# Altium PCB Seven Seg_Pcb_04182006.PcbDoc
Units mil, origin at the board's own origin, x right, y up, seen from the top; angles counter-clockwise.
Board outline 3624 x 2321 mil, 2 copper layers (Top Layer, Bottom Layer); 33 components, 44 nets, 144 pads, 3 vias.
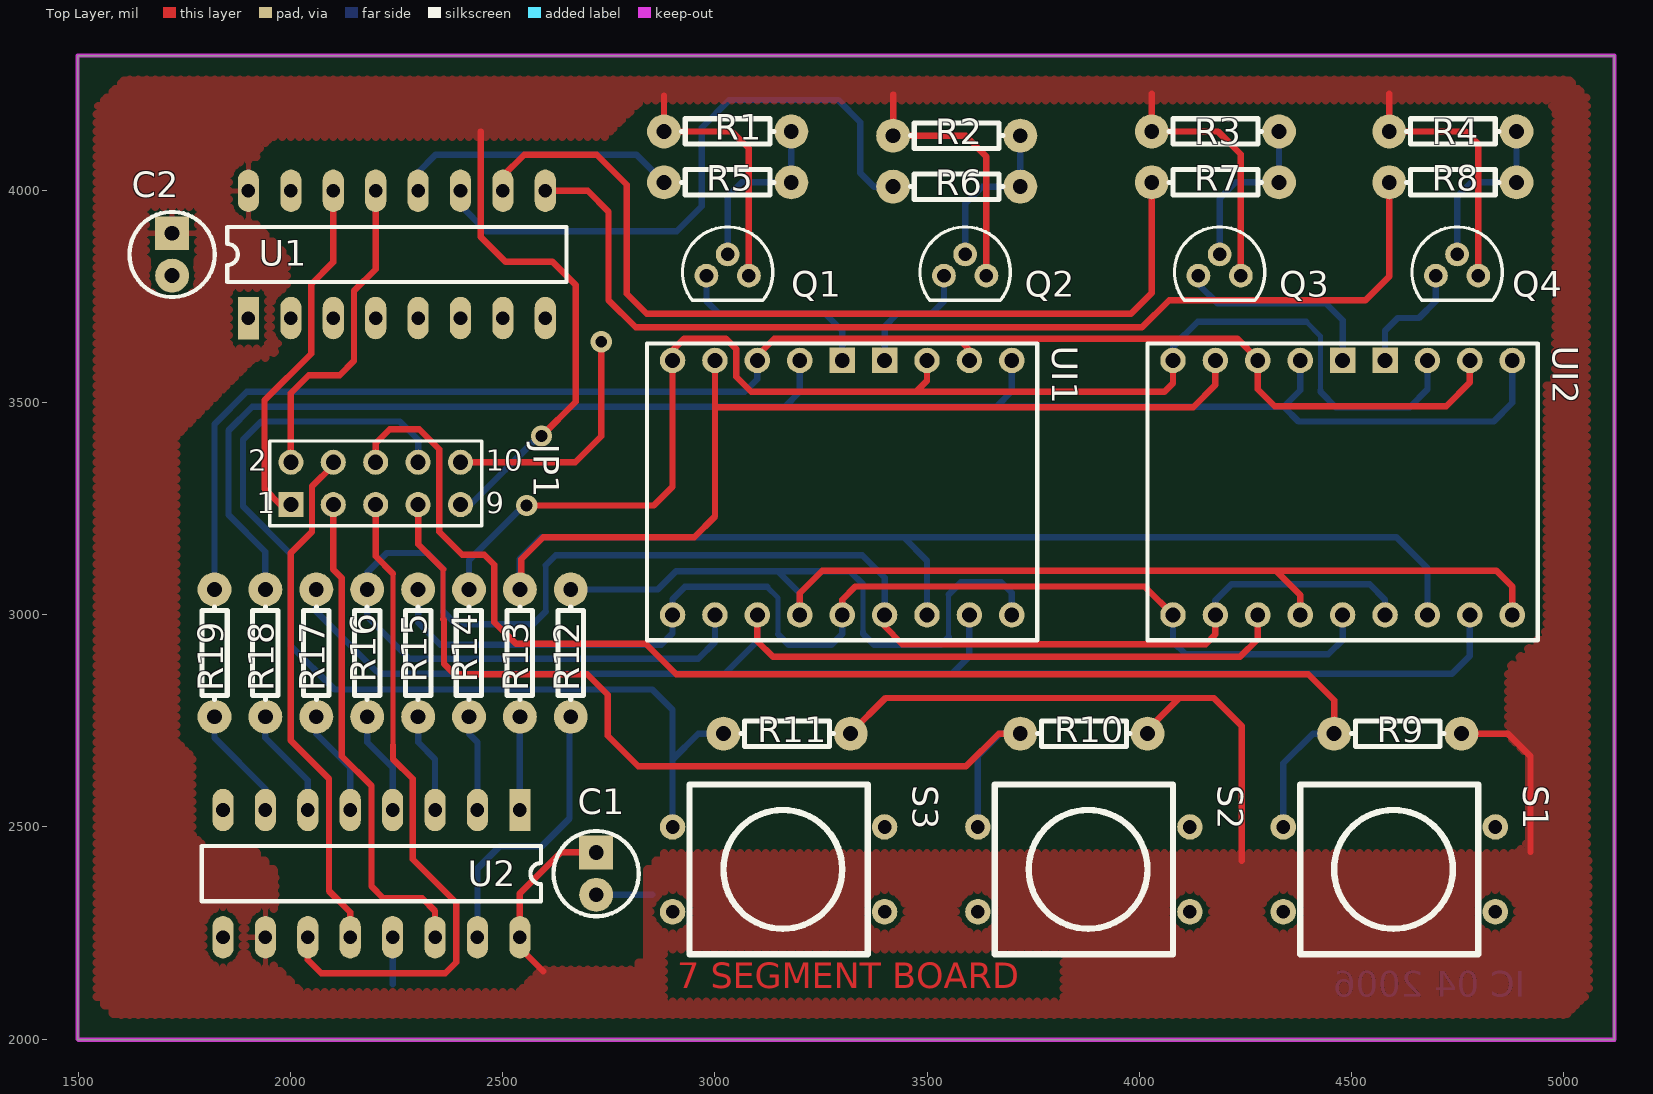
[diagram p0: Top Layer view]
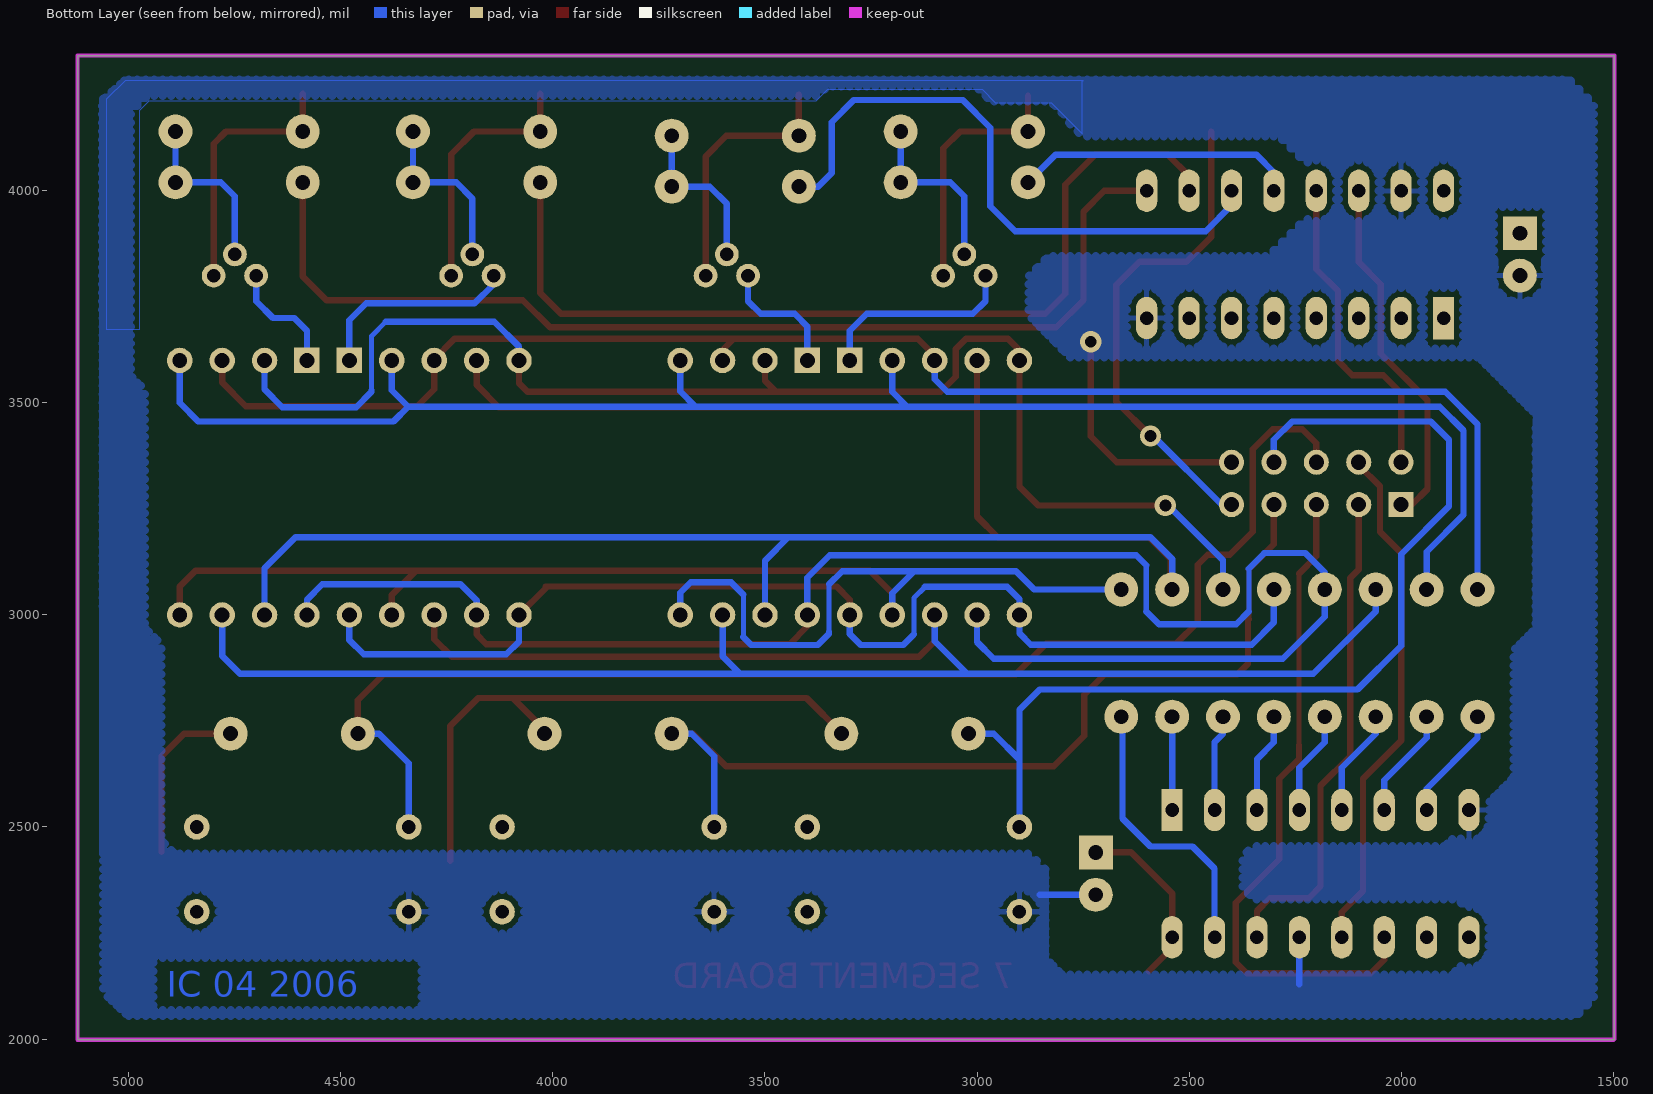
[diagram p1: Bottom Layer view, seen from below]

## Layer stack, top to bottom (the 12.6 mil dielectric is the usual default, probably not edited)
Top Layer: signal copper 1.4
Dielectric: dielectric 12.6, FR-4, Dk 4.8
Bottom Layer: signal copper 1.4

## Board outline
1497,4319 5121,4319 5121,1998 1497,1998

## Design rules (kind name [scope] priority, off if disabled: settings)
Clearance [All] p1: gap=12
ComponentClearance [All] p1: gap=10 collisioncheckmode=0
PlaneConnect [All] p1: planeconnectstyle=Relief reliefexpansion=20 reliefentries=4 reliefconductorwidth=12 reliefairgap=12
PolygonConnect [All] p1: connectstyle=Relief reliefconductorwidth=12 reliefentries=4 polygonreliefangle="90 Angle"
RoomDefinition SevenSeg_Sch_04172006 [InComponentClass('SevenSeg_Sch_04172006')] p1: confinementstyle=ConfineIn formatcopy=TRUE outline 1499,1997 5123,1997 5123,4324 1499,4324
RoutingLayers [All] p1: top layer=Horizontal bottom layer=Vertical
RoutingVias [All] p1: holewidth=28 width=50 viastyle="Through Hole" minholewidth=28 minwidth=50 maxholewidth=28 maxwidth=50
SolderMaskExpansion [All] p1: expansion=4
TestPointUsage [All] p1: valid=0 allowmultiple=FALSE
Testpoint [All] p1: side=15 testpointundercomponent=TRUE minsize=40 maxsize=100 preferedsize=60 minholesize=0 maxholesize=40 preferedholesize=32 testpointgrid=1 style=1023 order=-539222988
Width [All] p1: maxlimit=20 minlimit=12 preferedwidth=15
15 further rules are at their usual default settings.

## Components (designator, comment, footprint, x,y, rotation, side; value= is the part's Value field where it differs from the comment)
C1 "100nF" "CAP Circ/0.1" 2720,2440 r90 top
C2 "100nF" "CAP Circ/0.1" 1720,3900 r90 top
JP1 "Header 5X2" HDR2X5 2000,3260 r0 top
Q1 "PNP" BC548 3080,3800 r90 top
Q2 "PNP" BC548 3640,3800 r90 top
Q3 "PNP" BC548 4240,3800 r90 top
Q4 "PNP" BC548 4800,3800 r90 top
R1 "10K" RES 3180,4140 r180 top
R2 "10K" RES 3720,4130 r180 top
R3 "10K" RES 4330,4140 r180 top
R4 "10K" RES 4890,4140 r180 top
R5 "10K" RES 2880,4020 r0 top
R6 "10K" RES 3420,4010 r0 top
R7 "10K" RES 4030,4020 r0 top
R8 "10K" RES 4590,4020 r0 top
R9 "10k" RES 4460,2720 r0 top
R10 "10K" RES 3720,2720 r0 top
R11 "10K" RES 3020,2720 r0 top
R12 "220" RES 2660,2760 r90 top
R13 "220" RES 2540,2760 r90 top
R14 "220" RES 2420,2760 r90 top
R15 "220" RES 2300,2760 r90 top
R16 "220" RES 2180,2760 r90 top
R17 "220" RES 2060,2760 r90 top
R18 "220" RES 1940,2760 r90 top
R19 "220" RES 1820,2760 r90 top
S1 "SWITCH PB2" "SWITCH PB2" 4340,2500 r0 top
S2 "SWITCH PB2" "SWITCH PB2" 3620,2500 r0 top
S3 "SWITCH PB2" "SWITCH PB2" 2900,2500 r0 top
U1 "74HC139" DIP16 1900,3700 r90 top
U2 "74HC595" DIP16 2540,2540 r270 top
UI1 "SEVENSEG 2CA" SEVENTSEGMENT2 2900,3600 r0 top
UI2 "SEVENSEG 2CA" SEVENTSEGMENT2 4080,3600 r0 top

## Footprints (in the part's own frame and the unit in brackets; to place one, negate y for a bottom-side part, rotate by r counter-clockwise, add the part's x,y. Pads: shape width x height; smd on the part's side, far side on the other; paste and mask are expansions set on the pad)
BC548 [mil]
  round 56 hole 32: 1(0,0) 2(50,50) 3(0,100)
  silkscreen extent -59,-57 115,157
"CAP Circ/0.1" [mil]
  rect 80x80 hole 35: 1(0,0)
  round 80 hole 35: 2(-100,0)
  silkscreen extent -150,-100 50,100
DIP16 [mil]
  rect 100x50 hole 32: 1(0,0)
  oval 100x50 hole 32: 2(0,-100) 3(0,-200) 4(0,-300) 5(0,-400) 6(0,-500) 7(0,-600) 8(0,-700) 9(300,-700) 10(300,-600) 11(300,-500) 12(300,-400) 13(300,-300) 14(300,-200) 15(300,-100) 16(300,0)
  silkscreen extent 85,-750 215,50
HDR2X5 [mm]
  rect 1.5x1.5 hole 0.9: 1(0,0)
  round 1.5 hole 0.9: 2(0,2.54) 3(2.54,0) 4(2.54,2.54) 5(5.08,0) 6(5.08,2.54) 7(7.62,0) 8(7.62,2.54) 9(10.16,0) 10(10.16,2.54)
  silkscreen extent -1.27,-1.27 11.43,3.81
RES [mil]
  round 80 hole 35: 1(0,0) 2(300,0)
  silkscreen extent 41,-30 259,30
SEVENTSEGMENT2 [mil]
  round 60 hole 35: 1(0,0) 2(100,0) 3(200,0) 4(300,0) 7(600,0) 8(700,0) 9(800,0) 10(800,-600) 11(700,-600) 12(600,-600) 13(500,-600) 14(400,-600) 15(300,-600) 16(200,-600) 17(100,-600) 18(0,-600)
  rect 60x60 hole 35: 5(400,0) 6(500,0)
  silkscreen extent -60,-660 860,40
"SWITCH PB2" [mil]
  round 60 hole 32: 1(0,0) 2(0,-200) 3(500,0) 4(500,-200)
  silkscreen extent 40,-300 460,100

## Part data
C1 C2: library part CAPACITOR, "Capacitor"
JP1: "Header, 5-Pin, Dual row"
Q1 Q2 Q3 Q4: "PNP Transistor"
R1 R2 R3 R4 R5 R6 R7 R8 R9 R10 R11 R12 R13 R14 R15 R16 R17 R18 R19: library part RES
U1: "2-to-4 Decoder"
U2: "8 Bit Shift Register with Output Latches (3 STATE)"

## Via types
v1: diameter 50, hole 28, Top Layer to Bottom Layer, 3 vias

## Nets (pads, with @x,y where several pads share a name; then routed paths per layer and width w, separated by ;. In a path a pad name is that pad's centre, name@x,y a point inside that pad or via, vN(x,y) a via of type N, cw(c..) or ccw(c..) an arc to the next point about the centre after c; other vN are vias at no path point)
COM1: Q4.3 UI2.6 | length 279
  Bottom Layer w15: UI2.6 4580,3670 4610,3700 4660,3700 4700,3740 Q4.3
COM2: Q3.3 UI2.5 | length 490.2
  Bottom Layer w15: Q3.3 4140,3780 4185,3735 4440,3735 4480,3695 UI2.5
COM3: Q2.3 UI1.6 | length 304.9
  Bottom Layer w15: UI1.6 3400,3680 3430,3710 3510,3710 3540,3740 Q2.3
COM4: Q1.3 UI1.5 | length 479
  Bottom Layer w15: Q1.3 2980,3740 3010,3710 3260,3710 3300,3670 UI1.5
DEC0: JP1.2 U1.13 | length 765.6
  Top Layer w15: JP1.2 2000,3523 2042,3565 2115,3565 2149,3599 2149,3764 2200,3815 U1.13
DEC1: JP1.1 U1.14 | length 847.4
  Top Layer w15: JP1.1 1975,3260 1938,3297 1938,3506 2048,3616 2048,3780 2100,3832 U1.14
DSER: JP1.3 U2.14 | length 1173.3
  Top Layer w15: JP1.3 2100,3107 2120,3087 2120,2667 2190,2597 2190,2360 2218,2332 2310,2332 2340,2302 U2.14
GND: C1.2 C2.2 JP1.10 S1.2 S2.2 S3.2 U1.8 U1.15 U2.8 U2.13 | length 823.3
  Top Layer w15: JP1.10 2671,3360 2732,3421 v1(2732,3644)
  Bottom Layer w15: 2240,2129 U2.13 ; C1.2 2852,2340
LED1: R19.2 UI1.3 UI1.8 UI2.3 UI2.8 | length 3709.9
  Top Layer w15: UI1.3 3100,3611 3140,3651 4232,3651 4280,3603 4280,3532 4320,3492 4724,3492 4780,3548 UI2.8 ; 3574,3651 3600,3625 UI1.8
  Bottom Layer w15: R19.2 1820,3450 1896,3526 3070,3526 3100,3556 UI1.3
LED2: R18.2 UI1.4 UI1.9 UI2.4 UI2.9 | length 3966.5
  Bottom Layer w15: R18.2 1940,3149 1853,3236 1853,3435 1909,3491 4341,3491 ; 3165,3491 3200,3526 UI1.4 ; 3664,3491 3700,3527 UI1.9 ; UI2.4 4380,3530 4341,3491 ; UI2.9 4880,3500 4836,3456 4376,3456 4341,3491
LED3: R17.2 UI1.11 UI1.16 UI2.11 UI2.16 | length 4605.9
  Top Layer w15: UI1.16 3100,2938 3137,2901 4238,2901 4280,2943 UI2.16
  Bottom Layer w15: R17.2 2060,3008 2207,2861 4738,2861 4780,2903 UI2.11 ; 3023,2861 3100,2938 UI1.16 ; 3559,2861 3600,2902 UI1.11
LED4: R16.2 UI1.13 UI1.17 UI2.13 UI2.17 | length 4035.4
  Top Layer w15: UI1.13 3400,2973 3442,2931 4157,2931 4180,2954 UI2.17
  Bottom Layer w12: 2359,3008 2359,3109 ; 2601,3008 2601,3117
  Bottom Layer w15: 2359,3008 2389,2978 2571,2978 2601,3008 ; 2359,3109 2323,3145 2323,3146 2226,3146 2180,3100 2180,2996 2279,2897 2961,2897 3000,2936 UI1.17 ; 2601,3117 2625,3141 3347,3141 3400,3088 UI1.13 ; UI2.17 4180,3034 4218,3072 4544,3072 4580,3036 UI2.13
LED5: R15.2 UI1.14 UI1.18 UI2.14 UI2.18 | length 2773.1
  Top Layer w15: UI1.14 3300,3036 3331,3067 4017,3067 4017,3063 UI2.18
  Bottom Layer w12: 3123,3066 3149,3040 3149,2954
  Bottom Layer w15: R15.2 2300,2982 2352,2930 2873,2930 2900,2957 2900,3037 2929,3066 3123,3066 ; 3149,2954 3174,2929 3274,2929 3300,2955 UI1.14 ; UI2.18 4080,2937 4110,2907 4446,2907 4480,2941 UI2.14
LED6: R14.2 UI1.1 UI1.7 UI2.1 UI2.7 | length 3273.2
  Top Layer w15: v1(2556,3258) 2856,3258 2900,3302 2900,3624 2927,3651 3026,3651 3050,3627 3050,3562 3086,3526 4060,3526 4080,3546 UI2.1 ; 3474,3526 3500,3552 UI1.7
  Bottom Layer w12: 4394,3691 4428,3657 4428,3530
  Bottom Layer w15: R14.2 2420,3129 2549,3258 v1(2556,3258) ; UI2.1 4080,3633 4138,3691 4394,3691 ; 4428,3530 4428,3526 4464,3490 4638,3490 4680,3532 UI2.7
LED7: R13.2 UI1.2 UI1.12 UI2.2 UI2.12 | length 4777.8
  Top Layer w15: R13.2 2543,3063 2543,3131 2595,3183 2951,3183 3000,3232 UI1.2 ; 3000,3490 4128,3490 4180,3542 UI2.2
  Bottom Layer w15: R13.2 2540,3132 2591,3183 4607,3183 4680,3110 UI2.12 ; 3445,3183 3500,3128 UI1.12
LED8: R12.2 UI1.10 UI1.15 UI2.10 UI2.15 | length 3467.5
  Top Layer w15: UI1.15 3200,3051 3253,3104 4843,3104 4880,3067 UI2.10 ; 4323,3104 4380,3047 UI2.15
  Bottom Layer w12: 3349,2960 3349,3072 ; 3551,2948 3551,3048
  Bottom Layer w15: R12.2 2865,3060 2908,3103 3318,3103 3349,3072 ; 3148,3103 3200,3051 UI1.15 ; 3349,2960 3349,2956 3376,2929 3532,2929 3551,2948 ; 3551,3048 3580,3077 3675,3077 3700,3052 UI1.10
LSD1: R8.1 U1.9 | length 2517.5
  Top Layer w15: U1.9 2700,4000 2749,3951 2749,3742 2813,3678 4007,3678 4071,3742 4534,3742 4590,3798 R8.1
LSD2: R6.1 U1.11 | length 1470.4
  Bottom Layer w15: U1.11 2400,3966 2461,3905 2910,3905 2969,3964 2969,4149 3034,4214 3291,4214 3343,4162 3343,4042 3375,4010 R6.1
MSD1: R7.1 U1.10 | length 2172.9
  Top Layer w15: U1.10 2500,4035 2550,4085 2721,4085 2792,4014 2792,3757 2839,3710 3981,3710 4030,3759 R7.1
MSD2: R5.1 U1.12 | length 667.9
  Bottom Layer w15: U1.12 2300,4044 2341,4085 2815,4085 R5.1
NetQ1_2: Q1.2 R1.1 R5.2 | length 420.7
  Bottom Layer w15: Q1.2 3030,3987 3063,4020 R5.2 R1.1
NetQ2_2: Q2.2 R2.1 R6.2 | length 386.6
  Bottom Layer w15: Q2.2 3590,3970 3630,4010 R6.2 R2.1
NetQ3_2: Q3.2 R3.1 R7.2 | length 407.7
  Bottom Layer w15: Q3.2 4190,3982 4228,4020 R7.2 R3.1
NetQ4_2: Q4.2 R4.1 R8.2 | length 410.7
  Bottom Layer w15: Q4.2 4750,3987 4783,4020 R8.2 R4.1
NetR12_1: R12.1 U2.15 | length 677.9
  Bottom Layer w15: U2.15 2440,2402 2492,2454 2591,2454 2657,2520 R12.1@2657,2770
NetR13_1: R13.1 U2.1 | length 220
  Bottom Layer w15: U2.1 R13.1
NetR14_1: R14.1 U2.2 | length 228.3
  Bottom Layer w15: R14.1 2420,2720 2440,2700 U2.2
NetR15_1: R15.1 U2.3 | length 236.6
  Bottom Layer w15: R15.1 2300,2700 2340,2660 U2.3
NetR16_1: R16.1 U2.4 | length 244.9
  Bottom Layer w15: R16.1 2180,2700 2240,2640 U2.4
NetR17_1: R17.1 U2.5 | length 253.1
  Bottom Layer w15: R17.1 2060,2720 2140,2640 U2.5
NetR18_1: R18.1 U2.6 | length 261.4
  Bottom Layer w15: R18.1 1940,2710 2040,2610 U2.6
NetR19_1: R19.1 U2.7 | length 269.7
  Bottom Layer w15: R19.1 1820,2710 1940,2590 U2.7
NetU1_2: U1.2
NetU1_3: U1.3
NetU1_4: U1.4
NetU1_5: U1.5
NetU1_6: U1.6
NetU1_7: U1.7
SHCLK: JP1.5 U2.11 | length 1584.7
  Top Layer w12: 2241,2693 2241,3097
  Top Layer w15: U2.11 2040,2187 2072,2155 2364,2155 2390,2181 2390,2321 2287,2424 2287,2614 2241,2660 2241,2693 ; JP1.5 2200,3138 2241,3097
STCLK: JP1.4 U2.12 | length 1219.4
  Top Layer w15: JP1.4 2100,3353 2050,3303 2050,3196 2000,3146 2000,2704 2090,2614 2090,2349 2140,2299 U2.12
SW1: JP1.6 R9.1 S1.1 | length 3155.7
  Top Layer w15: JP1.6@2201,3360 JP1.6 2200,3405 2233,3438 2303,3438 2350,3391 2350,3196 2404,3142 2456,3142 2480,3118 2480,2983 2531,2932 2837,2932 2909,2860 4399,2860 4460,2799 R9.1
  Bottom Layer w15: S1.1 4340,2650 4410,2720 R9.1
SW2: JP1.7 R10.1 S2.1 | length 2237.2
  Top Layer w12: 2359,2990 2359,3108
  Top Layer w15: JP1.7 2300,3167 2359,3108 ; 2359,2990 2361,2988 2361,2885 2386,2860 2699,2860 2747,2812 2747,2715 2819,2643 3592,2643 3669,2720 R10.1
  Bottom Layer w15: S2.1 3620,2667 3673,2720 R10.1
SW3: JP1.8 R11.1 S3.1 | length 2418.2
  Bottom Layer w15: JP1.8 2300,3413 2257,3456 1930,3456 1887,3413 1887,3256 2000,3143 2000,2927 2103,2824 2852,2824 2900,2776 S3.1 ; 2900,2659 2961,2720 R11.1
VCC: C1.1 C2.1 JP1.9 Q1.1 Q2.1 Q3.1 Q4.1 R1.2 R2.2 R3.2 R4.2 R9.2 R10.2 R11.2 U1.16 U2.10 U2.16 | length 5871
  Top Layer w15: 2448,4140 2448,3891 2506,3833 2617,3833 2672,3778 2672,3503 v1(2591,3422) ; 2595,2160 2540,2215 2540,2343 2637,2440 C1.1 ; 2880,4224 R1.2 3040,4140 3080,4100 Q1.1 ; R11.2 3320,2722 3402,2804 4176,2804 4242,2738 4242,2420 ; 3420,4227 R2.2 3591,4130 3640,4081 Q2.1 ; R10.2 4020,2729 4095,2804 ; 4030,4229 R3.2 4186,4140 4240,4086 Q3.1 ; 4590,4229 R4.2 4771,4140 4800,4111 Q4.1 ; R9.2 4870,2720 4923,2667 4923,2441
  Bottom Layer w15: JP1.9 2423,3260 2585,3422 v1(2591,3422)
pads on no net: S1.3 S1.4 S2.3 S2.4 S3.3 S3.4 U1.1 U2.9

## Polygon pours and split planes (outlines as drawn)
VCC on Top Layer (hatched 90Degree grid 20 track 20, remove dead copper): 1541,4195 1608,4262 5013,4262 5056,4219 5056,3677 4982,3677 4982,4192 4960,4214 2827,4214 2740,4127 1954,4127 1919,4092 1919,3911 1926,3911 1990,3847 1990,3648 1948,3606 1822,3606 1668,3452 1542,3452 1542,4190
VCC on Top Layer (hatched 90Degree grid 20 track 20, remove dead copper): 1948,3606 1542,3606 1542,2099 1584,2057 5006,2057 5060,2109 5059,2438 2879,2438 2840,2399 2840,2200 2803,2163 2590,2163 2537,2110 2025,2110 1963,2172 1963,2395 1914,2444 1805,2444 1767,2482 1767,2664 1730,2701 1730,3422 1914,3606
VCC on Top Layer (hatched 90Degree grid 20 track 20): 4891,2438 4920,2467 4920,2667 4870,2717 4870,2872 4931,2933 4961,2963 4961,3542 4981,3562 4981,3677 5056,3677 5056,2438
GND on Bottom Layer (hatched 90Degree grid 20 track 20, remove dead copper): 1548,4207 1603,4262 2756,4262 2785,4233 2785,4162 2752,4129 2289,4129 2226,4066 2226,3934 2314,3846 2831,3846 2878,3799 2878,3707 2781,3607 1816.98,3606.98 1666,3456 1546,3456 1546,4205
GND on Bottom Layer (hatched 90Degree grid 20 track 20, remove dead copper): 1546,3466 1546,2095 1586,2055 5002,2055 5060,2109 5060,2437 2876,2437 2839,2400 2839,2192 2799,2152 1880,2152 1845,2187 1845,2307 1867,2329 2346,2329 2373,2356 2373,2431 2349,2455 1896,2455 1734,2617 1734,2917 1683,2968 1683,3460 1546,3460
GND on Bottom Layer (hatched 90Degree grid 20 track 20, remove dead copper): 2750,4260 5009,4260 5053,4216 5053,3674 4974,3674 4974,4190 4952,4212 3379,4212 3352,4239 2988,4239 2957,4208 2825,4208 2752,4135 2752,4260
GND on Bottom Layer (hatched 90Degree grid 20 track 20): 4892,2437 4924,2469 4924,2931 4962,2969 4962,3530 4995,3563 4995,4185 4956,4224 3375,4224 3352,4247 3003,4247 2967,4211 2827,4211 2756,4140 2756,4262 5008,4262 5063,4214 5060,2437

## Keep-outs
Keep-Out Layer:
  lines w10: 1497,2000 1497,4319 5121,4319 5121,1998 1499,1998 1497,2000

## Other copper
Top Layer:
  text "7 SEGMENT BOARD" at 2911,2120 h60
Bottom Layer:
  text "IC 04 2006" at 4911,2100 h60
